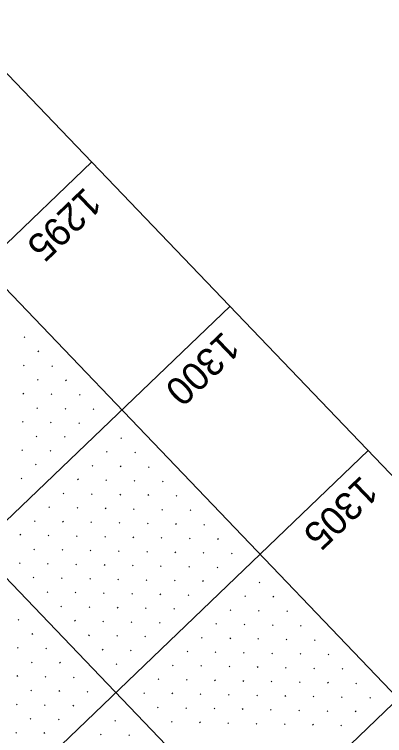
# Model space of a CAD drawing. Extents: x 2148987 to 2151117, y 142806 to 144993.
# Drawn here: x 2150450.2 to 2150542.8, y 144324.1 to 144504.6 of the extents above; entities that cross this region are included whole.
import ezdxf

# ---------------------------------------------------------------- set-up
doc = ezdxf.new("R2010")
doc.units = 0
for name, color, linetype in [('PR_PIER_PH3', 7, 'Continuous'), ('PR_Road_Concrete', 7, 'Continuous'), ('SHT_Profile_Grid_Minor', 7, 'Continuous'), ('Wall D Bore', 7, 'Continuous')]:
    doc.layers.add(name, color=color, linetype=linetype)

msp = doc.modelspace()

# ---------------------------------------------------------------- linework, layer by layer
at = {"layer": 'PR_PIER_PH3'}
for p, q in [((2150164.2, 144659.82), (2150510.15, 144298.83)), ((2150469.54, 144467.67), (2149332.4, 143377.92)), ((2150504.13, 144431.57), (2149367, 143341.82)), ((2150538.73, 144395.47), (2149401.59, 143305.72))]:
    msp.add_line(p, q, dxfattribs=at)
at = {"layer": 'PR_Road_Concrete'}
for p, q in [((2150200.3, 144694.42), (2150546.25, 144333.42)), ((2150573.32, 144359.37), (2149436.19, 143269.62))]:
    msp.add_line(p, q, dxfattribs=at)
msp.add_lwpolyline([(2150941.76, 143974.91), (2149804.63, 142885.16), (2149078.13, 143643.25), (2150215.26, 144733)], close=True, dxfattribs=at)
at = {"layer": 'SHT_Profile_Grid_Minor'}
for p, q in [((2150452.78, 144423.91), (2150452.6, 144423.73)), ((2150456.24, 144420.3), (2150456.06, 144420.12)), ((2150452.63, 144416.84), (2150452.45, 144416.67)), ((2150459.7, 144416.69), (2150459.52, 144416.51)), ((2150456.09, 144413.23), (2150455.91, 144413.06)), ((2150463.16, 144413.08), (2150462.98, 144412.91)), ((2150452.48, 144409.77), (2150452.3, 144409.6)), ((2150459.55, 144409.62), (2150459.37, 144409.45)), ((2150466.62, 144409.47), (2150466.44, 144409.3)), ((2150455.94, 144406.16), (2150455.76, 144405.99)), ((2150463.01, 144406.01), (2150462.83, 144405.84)), ((2150470.08, 144405.86), (2150469.9, 144405.69)), ((2150452.33, 144402.7), (2150452.15, 144402.53)), ((2150459.4, 144402.55), (2150459.22, 144402.38)), ((2150466.47, 144402.4), (2150466.29, 144402.23)), ((2150455.79, 144399.09), (2150455.61, 144398.92)), ((2150462.86, 144398.94), (2150462.68, 144398.77)), ((2150477, 144398.64), (2150476.82, 144398.47)), ((2150452.18, 144395.63), (2150452, 144395.46)), ((2150459.25, 144395.48), (2150459.07, 144395.31)), ((2150473.39, 144395.18), (2150473.21, 144395.01)), ((2150480.46, 144395.03), (2150480.28, 144394.86)), ((2150455.64, 144392.02), (2150455.46, 144391.85)), ((2150469.78, 144391.72), (2150469.6, 144391.55)), ((2150476.85, 144391.57), (2150476.67, 144391.4)), ((2150483.92, 144391.42), (2150483.74, 144391.25)), ((2150452.03, 144388.56), (2150451.85, 144388.39)), ((2150466.17, 144388.26), (2150465.99, 144388.09)), ((2150473.24, 144388.11), (2150473.06, 144387.94)), ((2150480.31, 144387.96), (2150480.13, 144387.79)), ((2150487.38, 144387.81), (2150487.2, 144387.64)), ((2150462.56, 144384.8), (2150462.38, 144384.63)), ((2150469.63, 144384.65), (2150469.45, 144384.48)), ((2150476.7, 144384.5), (2150476.52, 144384.33)), ((2150483.77, 144384.35), (2150483.59, 144384.18)), ((2150490.84, 144384.2), (2150490.66, 144384.03)), ((2150458.95, 144381.34), (2150458.77, 144381.17)), ((2150466.02, 144381.19), (2150465.84, 144381.02)), ((2150473.09, 144381.04), (2150472.91, 144380.87)), ((2150480.16, 144380.89), (2150479.98, 144380.72)), ((2150487.23, 144380.74), (2150487.05, 144380.57)), ((2150494.3, 144380.59), (2150494.12, 144380.42)), ((2150455.34, 144377.88), (2150455.16, 144377.71)), ((2150462.41, 144377.73), (2150462.23, 144377.56)), ((2150469.48, 144377.58), (2150469.3, 144377.41)), ((2150476.55, 144377.43), (2150476.37, 144377.26)), ((2150483.62, 144377.28), (2150483.44, 144377.11)), ((2150490.69, 144377.13), (2150490.51, 144376.96)), ((2150497.76, 144376.98), (2150497.57, 144376.81)), ((2150451.73, 144374.42), (2150451.55, 144374.25)), ((2150458.8, 144374.27), (2150458.62, 144374.1)), ((2150465.87, 144374.12), (2150465.69, 144373.95)), ((2150472.94, 144373.97), (2150472.76, 144373.8)), ((2150480.01, 144373.82), (2150479.83, 144373.65)), ((2150487.08, 144373.67), (2150486.9, 144373.5)), ((2150494.15, 144373.52), (2150493.96, 144373.35)), ((2150501.21, 144373.37), (2150501.03, 144373.2)), ((2150455.19, 144370.81), (2150455.01, 144370.64)), ((2150462.26, 144370.66), (2150462.08, 144370.49)), ((2150469.33, 144370.51), (2150469.15, 144370.34)), ((2150476.4, 144370.36), (2150476.22, 144370.19)), ((2150483.47, 144370.21), (2150483.29, 144370.04)), ((2150490.54, 144370.06), (2150490.35, 144369.89)), ((2150497.6, 144369.91), (2150497.42, 144369.74)), ((2150504.67, 144369.76), (2150504.49, 144369.59)), ((2150451.58, 144367.35), (2150451.4, 144367.18)), ((2150458.65, 144367.2), (2150458.47, 144367.03)), ((2150465.72, 144367.05), (2150465.54, 144366.88)), ((2150472.79, 144366.9), (2150472.61, 144366.73)), ((2150479.86, 144366.75), (2150479.68, 144366.58)), ((2150486.93, 144366.6), (2150486.75, 144366.43)), ((2150493.99, 144366.45), (2150493.81, 144366.28)), ((2150501.06, 144366.3), (2150500.88, 144366.13)), ((2150455.04, 144363.74), (2150454.86, 144363.57)), ((2150462.11, 144363.59), (2150461.93, 144363.42)), ((2150469.18, 144363.44), (2150469, 144363.27)), ((2150476.25, 144363.29), (2150476.07, 144363.12)), ((2150483.32, 144363.14), (2150483.14, 144362.97)), ((2150490.39, 144362.99), (2150490.2, 144362.82)), ((2150497.45, 144362.84), (2150497.27, 144362.67)), ((2150511.59, 144362.54), (2150511.41, 144362.37)), ((2150458.5, 144360.13), (2150458.32, 144359.96)), ((2150465.57, 144359.98), (2150465.39, 144359.81)), ((2150472.64, 144359.83), (2150472.46, 144359.66)), ((2150479.71, 144359.68), (2150479.53, 144359.51)), ((2150486.78, 144359.53), (2150486.59, 144359.36)), ((2150493.84, 144359.38), (2150493.66, 144359.21)), ((2150507.98, 144359.08), (2150507.8, 144358.91)), ((2150515.05, 144358.93), (2150514.87, 144358.76)), ((2150461.96, 144356.52), (2150461.78, 144356.35)), ((2150469.03, 144356.37), (2150468.85, 144356.2)), ((2150476.1, 144356.22), (2150475.92, 144356.05)), ((2150483.17, 144356.07), (2150482.98, 144355.9)), ((2150490.23, 144355.92), (2150490.05, 144355.75)), ((2150504.37, 144355.62), (2150504.19, 144355.45)), ((2150511.44, 144355.47), (2150511.26, 144355.3)), ((2150518.51, 144355.32), (2150518.33, 144355.15)), ((2150451.28, 144353.21), (2150451.1, 144353.04)), ((2150465.42, 144352.91), (2150465.24, 144352.74)), ((2150472.49, 144352.76), (2150472.31, 144352.59)), ((2150479.56, 144352.61), (2150479.37, 144352.44)), ((2150486.62, 144352.46), (2150486.44, 144352.29)), ((2150500.76, 144352.16), (2150500.58, 144351.99)), ((2150507.83, 144352.01), (2150507.65, 144351.84)), ((2150514.9, 144351.86), (2150514.72, 144351.69)), ((2150521.97, 144351.71), (2150521.79, 144351.54)), ((2150454.74, 144349.6), (2150454.56, 144349.43)), ((2150468.88, 144349.3), (2150468.7, 144349.13)), ((2150475.95, 144349.15), (2150475.76, 144348.98)), ((2150483.01, 144349), (2150482.83, 144348.83)), ((2150497.15, 144348.7), (2150496.97, 144348.53)), ((2150504.22, 144348.55), (2150504.04, 144348.38)), ((2150511.29, 144348.4), (2150511.11, 144348.23)), ((2150518.36, 144348.25), (2150518.18, 144348.08)), ((2150525.43, 144348.1), (2150525.25, 144347.93)), ((2150451.13, 144346.14), (2150450.95, 144345.97)), ((2150458.2, 144345.99), (2150458.02, 144345.82)), ((2150472.34, 144345.69), (2150472.15, 144345.52)), ((2150479.4, 144345.54), (2150479.22, 144345.37)), ((2150493.54, 144345.24), (2150493.36, 144345.07)), ((2150500.61, 144345.09), (2150500.43, 144344.92)), ((2150507.68, 144344.94), (2150507.5, 144344.77)), ((2150514.75, 144344.79), (2150514.57, 144344.62)), ((2150521.82, 144344.64), (2150521.64, 144344.47)), ((2150528.89, 144344.49), (2150528.71, 144344.32)), ((2150454.59, 144342.53), (2150454.41, 144342.36)), ((2150461.66, 144342.38), (2150461.48, 144342.21)), ((2150475.79, 144342.08), (2150475.61, 144341.91)), ((2150489.93, 144341.78), (2150489.75, 144341.61)), ((2150497, 144341.63), (2150496.82, 144341.46)), ((2150504.07, 144341.48), (2150503.89, 144341.31)), ((2150511.14, 144341.33), (2150510.96, 144341.16)), ((2150518.21, 144341.18), (2150518.03, 144341.01)), ((2150525.28, 144341.03), (2150525.1, 144340.86)), ((2150532.35, 144340.88), (2150532.17, 144340.71)), ((2150450.98, 144339.07), (2150450.8, 144338.9)), ((2150458.05, 144338.92), (2150457.87, 144338.75)), ((2150465.12, 144338.77), (2150464.93, 144338.6)), ((2150486.32, 144338.32), (2150486.14, 144338.15)), ((2150493.39, 144338.17), (2150493.21, 144338)), ((2150500.46, 144338.02), (2150500.28, 144337.85)), ((2150507.53, 144337.87), (2150507.35, 144337.7)), ((2150514.6, 144337.72), (2150514.42, 144337.55)), ((2150521.67, 144337.57), (2150521.49, 144337.4)), ((2150528.74, 144337.42), (2150528.56, 144337.25)), ((2150535.81, 144337.27), (2150535.63, 144337.1)), ((2150454.44, 144335.46), (2150454.26, 144335.29)), ((2150461.51, 144335.31), (2150461.32, 144335.14)), ((2150468.57, 144335.16), (2150468.39, 144334.99)), ((2150482.71, 144334.86), (2150482.53, 144334.69)), ((2150489.78, 144334.71), (2150489.6, 144334.54)), ((2150496.85, 144334.56), (2150496.67, 144334.39)), ((2150503.92, 144334.41), (2150503.74, 144334.24)), ((2150510.99, 144334.26), (2150510.81, 144334.09)), ((2150518.06, 144334.11), (2150517.88, 144333.94)), ((2150525.13, 144333.96), (2150524.95, 144333.79)), ((2150532.2, 144333.81), (2150532.02, 144333.64)), ((2150539.27, 144333.66), (2150539.09, 144333.49)), ((2150450.83, 144332), (2150450.65, 144331.83)), ((2150457.9, 144331.85), (2150457.71, 144331.68)), ((2150464.96, 144331.7), (2150464.78, 144331.53)), ((2150486.17, 144331.25), (2150485.99, 144331.08)), ((2150493.24, 144331.1), (2150493.06, 144330.93)), ((2150500.31, 144330.95), (2150500.13, 144330.78)), ((2150507.38, 144330.8), (2150507.2, 144330.63)), ((2150514.45, 144330.65), (2150514.27, 144330.48)), ((2150521.52, 144330.5), (2150521.34, 144330.33)), ((2150528.59, 144330.35), (2150528.41, 144330.18)), ((2150535.66, 144330.2), (2150535.48, 144330.03)), ((2150454.29, 144328.39), (2150454.11, 144328.22)), ((2150461.35, 144328.24), (2150461.17, 144328.07)), ((2150475.49, 144327.94), (2150475.31, 144327.77)), ((2150489.63, 144327.64), (2150489.45, 144327.47)), ((2150496.7, 144327.49), (2150496.52, 144327.32)), ((2150503.77, 144327.34), (2150503.59, 144327.17)), ((2150510.84, 144327.19), (2150510.66, 144327.02)), ((2150517.91, 144327.04), (2150517.73, 144326.87)), ((2150524.98, 144326.89), (2150524.8, 144326.72)), ((2150532.05, 144326.74), (2150531.87, 144326.57)), ((2150450.68, 144324.94), (2150450.5, 144324.76)), ((2150457.75, 144324.78), (2150457.56, 144324.61)), ((2150471.88, 144324.48), (2150471.7, 144324.31)), ((2150478.95, 144324.33), (2150478.77, 144324.16))]:
    msp.add_line(p, q, dxfattribs=at)

# ---------------------------------------------------------------- texts
at = {"layer": 'Wall D Bore'}
for s, p in [('1295', (2150467.83, 144461.66)), ('1300', (2150502.42, 144425.56)), ('1305', (2150537.02, 144389.46))]:
    msp.add_text(s, height=7, rotation=223.7809, dxfattribs=at).set_placement(p)

doc.saveas('drawing.dxf')
